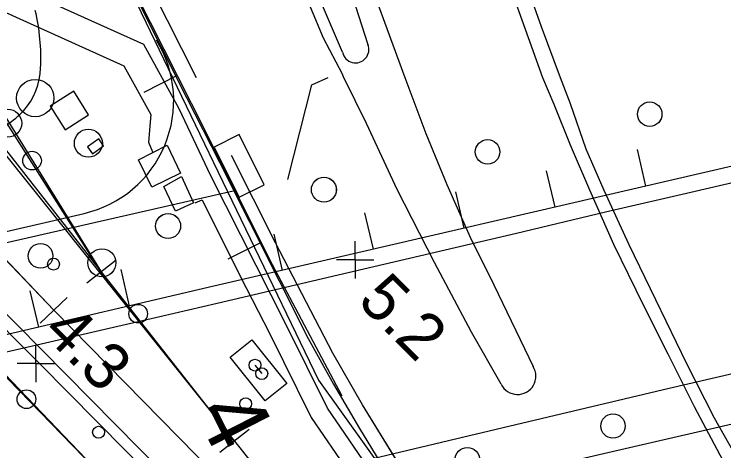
# Model space of a CAD drawing. Extents: x 1596643 to 1597288, y 13057194 to 13057957.
# Drawn here: x 1596926.19 to 1596964.23, y 13057439.15 to 13057462.53 of the extents above; entities that cross this region are included whole.
import ezdxf

# ---------------------------------------------------------------- set-up
doc = ezdxf.new("R2010")
doc.units = 0
for name, color, linetype in [('A Isolerskarv P', 7, 'Continuous'), ('A spårmitt L', 7, 'Continuous'), ('B kabelränna 400-500 mm NK L', 7, 'Continuous'), ('B kabelränna större än 500 mm NK L', 7, 'Continuous'), ('B växel linjevikt 0 L', 7, 'Continuous'), ('BAS bro ej def L', 7, 'Continuous'), ('BAS bro kantbalk ej def L', 7, 'Continuous'), ('BAS bropelare stöd ej def L', 7, 'Continuous'), ('BAS dagvatten brunn P', 7, 'Continuous'), ('BAS gång- cykelväg skymd L', 7, 'Continuous'), ('BAS jvg-bro kantbalk L', 7, 'Continuous'), ('BAS jvg-bro landfäste vinge L', 7, 'Continuous'), ('BAS Level 15', 7, 'Continuous'), ('BAS Level 16', 7, 'Continuous'), ('BAS Level 18', 7, 'Continuous'), ('BAS Level 29', 7, 'Continuous'), ('BAS Level 36', 7, 'Continuous'), ('BAS Level 37', 7, 'Continuous'), ('BAS markytetext T', 7, 'Continuous'), ('BAS stödmur fot L', 7, 'Continuous'), ('BAS stödmur krön L', 7, 'Continuous'), ('BAS vägbanekant L', 7, 'Continuous'), ('BAS vägbanekant skymd L', 7, 'Continuous'), ('C skåp kartsymbol P', 7, 'Continuous'), ('C skåp L', 7, 'Continuous'), ('C transformator L', 7, 'Continuous'), ('E ktlstolpe normal centrum P', 7, 'Continuous'), ('E sträva centrum P', 7, 'Continuous'), ('F signal fristående P', 7, 'Continuous')]:
    doc.layers.add(name, color=color, linetype=linetype)

msp = doc.modelspace()

# ---------------------------------------------------------------- linework, layer by layer
at = {"layer": 'A Isolerskarv P'}
for centre in [(1596925.84, 13057456.695), (1596925.84, 13057456.695), (1596930.886, 13057449.22), (1596930.886, 13057449.22)]:
    msp.add_circle(centre, 0.75, dxfattribs=at)
at = {"layer": 'A spårmitt L'}
for points in [[(1596861.603, 13057516.009), (1596866.442, 13057509.391), (1596878.849, 13057493.781), (1596895.097, 13057475.302), (1596900.34, 13057469.714), (1596931.231, 13057437.468), (1596933.8, 13057434.835)], [(1596887.988, 13057492.75), (1596889.66, 13057490.516), (1596900.094, 13057476.776), (1596906.53, 13057469.464), (1596928.328, 13057446.663), (1596936.899, 13057437.942), (1596957.336, 13057417.351), (1597001.928, 13057371.989), (1597034.879, 13057338.506), (1597063.764, 13057309.15)], [(1596906.028, 13057487.38), (1596921.777, 13057463.002), (1596931.207, 13057448.128)], [(1596907.066, 13057477.919), (1596920.191, 13057461.87), (1596938.351, 13057439.217), (1596949.208, 13057425.541)]]:
    msp.add_lwpolyline(points, dxfattribs=at)
at = {"layer": 'B kabelränna 400-500 mm NK L'}
msp.add_lwpolyline([(1596883.038, 13057480.441), (1596889.091, 13057474.53), (1596902.563, 13057461.987), (1596910.703, 13057454.289), (1596911.093, 13057454.69), (1596913.886, 13057457.525), (1596927.553, 13057443.815), (1596936.728, 13057434.552), (1596947.807, 13057423.165), (1596958.841, 13057412.087), (1596959.17, 13057412.506), (1596945.763, 13057426.086), (1596935.532, 13057436.607), (1596925.003, 13057447.233), (1596913.927, 13057458.386), (1596910.643, 13057455.068), (1596902.92, 13057462.372), (1596891.14, 13057473.364), (1596883.436, 13057480.826)], dxfattribs=at)
at = {"layer": 'B kabelränna större än 500 mm NK L'}
for points in [[(1596912.644, 13057489.282), (1596912.288, 13057489.11), (1596916.306, 13057480.961), (1596922.107, 13057468.716), (1596924.964, 13057462.97), (1596932.073, 13057459.771), (1596933.51, 13057457.153), (1596933.386, 13057455.673), (1596933.609, 13057455.161)], [(1596935.025, 13057457.474), (1596933.135, 13057460.919), (1596926.056, 13057464.105), (1596923.449, 13057469.348)], [(1596966.736, 13057411.707), (1596965.667, 13057412.984), (1596959.924, 13057419.384), (1596956.53, 13057423.046), (1596952.713, 13057427.821), (1596945.579, 13057437.659), (1596942.975, 13057441.442), (1596940.764, 13057445.894), (1596936.73, 13057453.881), (1596935.025, 13057457.474)], [(1596935.897, 13057452.432), (1596936.26, 13057452.588)], [(1596936.26, 13057452.588), (1596938.339, 13057448.441), (1596939.871, 13057445.444), (1596942.111, 13057440.933), (1596944.761, 13057437.083), (1596949.235, 13057430.863), (1596951.919, 13057427.212), (1596955.772, 13057422.393), (1596959.185, 13057418.71), (1596965.564, 13057411.602)]]:
    msp.add_lwpolyline(points, dxfattribs=at)
at = {"layer": 'B växel linjevikt 0 L'}
for p, q in [((1596930.874, 13057448.745), (1596921.659, 13057463.592)), ((1596930.874, 13057448.745), (1596921.659, 13057463.592)), ((1596930.874, 13057448.745), (1596920.075, 13057462.483)), ((1596930.874, 13057448.745), (1596920.075, 13057462.483)), ((1596928.31, 13057446.676), (1596915.42, 13057460.223)), ((1596928.31, 13057446.676), (1596915.42, 13057460.223)), ((1596930.874, 13057437.838), (1596918.078, 13057450.985)), ((1596930.874, 13057437.838), (1596918.078, 13057450.985)), ((1596931.661, 13057449.363), (1596930.088, 13057448.127)), ((1596931.661, 13057449.363), (1596930.088, 13057448.127)), ((1596938.006, 13057439.672), (1596930.874, 13057448.745)), ((1596938.006, 13057439.672), (1596930.874, 13057448.745)), ((1596929.034, 13057447.365), (1596927.586, 13057445.986)), ((1596929.034, 13057447.365), (1596927.586, 13057445.986)), ((1596938.792, 13057440.29), (1596937.22, 13057439.054)), ((1596938.792, 13057440.29), (1596937.22, 13057439.054))]:
    msp.add_line(p, q, dxfattribs=at)
at = {"layer": 'BAS bro ej def L'}
for points in [[(1596943.79, 13057460.493), (1596941.475, 13057465.89), (1596939.506, 13057470.621), (1596937.752, 13057475.401), (1596935.601, 13057481.7), (1596933.54, 13057487.886), (1596931.689, 13057493.846), (1596930.024, 13057499.204), (1596929.355, 13057502.374), (1596928.751, 13057505.014), (1596928.377, 13057506.696), (1596928.227, 13057507.736)], [(1596931.231, 13057501.323), (1596933.825, 13057493.971), (1596936.089, 13057487.752), (1596938.584, 13057480.625), (1596940.277, 13057475.775), (1596943.187, 13057467.026), (1596945.148, 13057460.913)]]:
    msp.add_lwpolyline(points, dxfattribs=at)
msp.add_arc((1596944.488, 13057460.641), 0.714, 191.9714, 22.3976, dxfattribs=at)
at = {"layer": 'BAS bro kantbalk ej def L'}
for p, q in [((1596930.096, 13057468.679), (1596935.426, 13057458.074)), ((1596935.426, 13057458.074), (1596937.194, 13057454.611))]:
    msp.add_line(p, q, dxfattribs=at)
at = {"layer": 'BAS bropelare stöd ej def L'}
for centre, radius in [((1596960.261, 13057457.18), 0.656), ((1596960.261, 13057457.18), 0.655), ((1596951.564, 13057455.161), 0.655), ((1596951.564, 13057455.161), 0.655), ((1596942.789, 13057453.136), 0.669), ((1596942.789, 13057453.136), 0.668), ((1596934.438, 13057451.188), 0.67), ((1596934.438, 13057451.189), 0.67), ((1596927.6, 13057449.592), 0.661), ((1596927.6, 13057449.592), 0.661), ((1596958.288, 13057440.48), 0.653), ((1596958.289, 13057440.48), 0.652), ((1596950.479, 13057438.666), 0.666), ((1596950.479, 13057438.666), 0.666)]:
    msp.add_circle(centre, radius, dxfattribs=at)
at = {"layer": 'BAS dagvatten brunn P'}
msp.add_line((1596938.247, 13057454.405), (1596938.247, 13057454.405), dxfattribs=at)
msp.add_line((1596938.247, 13057454.405), (1596938.247, 13057454.405), dxfattribs=at)
msp.add_lwpolyline([(1596936.902, 13057455.407), (1596938.252, 13057452.728), (1596939.592, 13057453.403), (1596938.242, 13057456.082)], close=True, dxfattribs=at)
msp.add_lwpolyline([(1596936.902, 13057455.407), (1596938.252, 13057452.728), (1596939.592, 13057453.403), (1596938.242, 13057456.082)], close=True, dxfattribs=at)
at = {"layer": 'BAS gång- cykelväg skymd L'}
msp.add_line((1596904.78, 13057446.035), (1596929.935, 13057451.867), dxfattribs=at)
for centre, radius, start, end in [((1596916.548, 13057460.18), 11.068, 357.2481, 13.3555), ((1596928.554, 13057457.895), 6.184, 282.9061, 31.6951), ((1596924.016, 13057459.756), 3.589, 318.4684, 358.2838), ((1596922.19, 13057461.743), 6.28, 294.2396, 315.9406)]:
    msp.add_arc(centre, radius, start, end, dxfattribs=at)
at = {"layer": 'BAS jvg-bro kantbalk L'}
for p, q in [((1596937.194, 13057454.611), (1596940.4, 13057448.249)), ((1596940.4, 13057448.249), (1596941.949, 13057445.162)), ((1596941.949, 13057445.162), (1596943.298, 13057442.722)), ((1596943.298, 13057442.722), (1596944.705, 13057440.352)), ((1596944.705, 13057440.352), (1596946.147, 13057437.981))]:
    msp.add_line(p, q, dxfattribs=at)
for centre, radius, start, end in [((1596754.249, 13057209.032), 283.999, 44.7736, 55.47706), ((1596747.882, 13057200.444), 290.055, 49.94104, 56.21521)]:
    msp.add_arc(centre, radius, start, end, dxfattribs=at)
at = {"layer": 'BAS jvg-bro landfäste vinge L'}
msp.add_lwpolyline([(1596908.173, 13057446.295), (1596908.918, 13057446.461), (1596937.924, 13057453.08)], dxfattribs=at)
at = {"layer": 'BAS Level 15'}
for centre in [(1596927.145, 13057454.69), (1596927.145, 13057454.69), (1596932.833, 13057446.493), (1596932.833, 13057446.493), (1596926.844, 13057441.914), (1596926.844, 13057441.914)]:
    msp.add_circle(centre, 0.5, dxfattribs=at)
at = {"layer": 'BAS Level 16'}
for p, q in [((1596944.473, 13057449.371), (1596944.473, 13057450.371)), ((1596944.473, 13057449.371), (1596944.473, 13057450.371)), ((1596944.473, 13057449.371), (1596943.473, 13057449.371)), ((1596944.473, 13057449.371), (1596943.473, 13057449.371)), ((1596944.473, 13057449.371), (1596945.473, 13057449.371)), ((1596944.473, 13057449.371), (1596944.473, 13057448.371)), ((1596944.473, 13057449.371), (1596945.473, 13057449.371)), ((1596944.473, 13057449.371), (1596944.473, 13057448.371)), ((1596927.344, 13057443.834), (1596927.344, 13057444.834)), ((1596927.344, 13057443.834), (1596927.344, 13057444.834)), ((1596927.344, 13057443.834), (1596926.344, 13057443.834)), ((1596927.344, 13057443.834), (1596926.344, 13057443.834)), ((1596927.344, 13057443.834), (1596928.344, 13057443.834)), ((1596927.344, 13057443.834), (1596927.344, 13057442.834)), ((1596927.344, 13057443.834), (1596928.344, 13057443.834)), ((1596927.344, 13057443.834), (1596927.344, 13057442.834))]:
    msp.add_line(p, q, dxfattribs=at)
at = {"layer": 'BAS Level 18'}
for p, q in [((1596934.926, 13057459.248), (1596933.141, 13057458.346)), ((1596934.926, 13057459.248), (1596933.141, 13057458.346)), ((1596960.056, 13057453.331), (1596959.604, 13057455.279)), ((1596960.056, 13057453.331), (1596959.604, 13057455.279)), ((1596955.185, 13057452.201), (1596954.733, 13057454.149)), ((1596955.185, 13057452.201), (1596954.733, 13057454.149)), ((1596950.314, 13057451.072), (1596949.862, 13057453.02)), ((1596950.314, 13057451.072), (1596949.862, 13057453.02)), ((1596945.443, 13057449.943), (1596944.991, 13057451.891)), ((1596945.443, 13057449.943), (1596944.991, 13057451.891)), ((1596940.573, 13057448.813), (1596940.121, 13057450.761)), ((1596940.573, 13057448.813), (1596940.121, 13057450.761)), ((1596939.421, 13057450.315), (1596937.634, 13057449.417)), ((1596939.421, 13057450.315), (1596937.634, 13057449.417)), ((1596932.371, 13057446.907), (1596931.917, 13057448.855)), ((1596932.371, 13057446.907), (1596931.917, 13057448.855)), ((1596927.501, 13057445.773), (1596927.047, 13057447.721)), ((1596927.501, 13057445.773), (1596927.047, 13057447.721))]:
    msp.add_line(p, q, dxfattribs=at)
at = {"layer": 'BAS Level 29'}
for centre in [(1596928.293, 13057449.149), (1596928.293, 13057449.149), (1596939.096, 13057443.739), (1596939.096, 13057443.739), (1596939.459, 13057443.286), (1596939.459, 13057443.286), (1596938.596, 13057441.672), (1596938.596, 13057441.672), (1596930.71, 13057440.147), (1596930.71, 13057440.147)]:
    msp.add_circle(centre, 0.318, dxfattribs=at)
at = {"layer": 'BAS Level 37'}
for points in [[(1596929.415, 13057470.053), (1596934.679, 13057459.15)], [(1596934.679, 13057459.15), (1596942.51, 13057442.931), (1596946.333, 13057437.601), (1596952.505, 13057428.568), (1596955.404, 13057424.94), (1596958.328, 13057421.412), (1596968.373, 13057410.821)]]:
    msp.add_lwpolyline(points, dxfattribs=at)
at = {"layer": 'BAS stödmur fot L'}
msp.add_lwpolyline([(1596940.857, 13057453.679), (1596942.144, 13057458.756), (1596943.017, 13057459.15)], dxfattribs=at)
at = {"layer": 'BAS stödmur krön L'}
for p, q in [((1596968.602, 13057455.312), (1596936.897, 13057447.961)), ((1596936.897, 13057447.961), (1596913.236, 13057442.45))]:
    msp.add_line(p, q, dxfattribs=at)
msp.add_lwpolyline([(1596910.214, 13057513.767), (1596911.127, 13057509.619), (1596913.141, 13057503.998), (1596916.093, 13057497.121), (1596921.06, 13057486.966), (1596925.519, 13057477.89), (1596930.551, 13057467.911), (1596935.677, 13057457.761), (1596940.017, 13057449.129), (1596943.748, 13057442.095)], dxfattribs=at)
at = {"layer": 'BAS vägbanekant L'}
for p, q in [((1596940.197, 13057450.291), (1596937.839, 13057454.961)), ((1596943.263, 13057444.387), (1596940.197, 13057450.291)), ((1596944.866, 13057441.615), (1596943.263, 13057444.387)), ((1596947.373, 13057437.534), (1596944.866, 13057441.615))]:
    msp.add_line(p, q, dxfattribs=at)
for points in [[(1596909.852, 13057526.126), (1596909.933, 13057524.265), (1596909.962, 13057521.856), (1596910.034, 13057520.017), (1596910.117, 13057518.411), (1596910.4, 13057516.123), (1596910.678, 13057514.709), (1596910.915, 13057513.499), (1596911.213, 13057512.126), (1596911.593, 13057510.742), (1596912.272, 13057508.493), (1596913.245, 13057505.826), (1596914.218, 13057503.383), (1596915.393, 13057500.633), (1596917.977, 13057495.093), (1596921.539, 13057487.973), (1596925.462, 13057480.018), (1596929.708, 13057471.482), (1596935.948, 13057459.15)], [(1596927.844, 13057508.45), (1596927.898, 13057507.778), (1596928.004, 13057506.639), (1596928.183, 13057505.683), (1596928.641, 13057503.862), (1596929.356, 13057500.566), (1596930.104, 13057497.788), (1596930.721, 13057495.174), (1596931.96, 13057491.022), (1596933.249, 13057486.525), (1596934.209, 13057483.411), (1596935.201, 13057480.632), (1596936.192, 13057477.68), (1596937.696, 13057473.73), (1596939.473, 13057469.291), (1596941.008, 13057465.453), (1596942.745, 13057461.268), (1596943.762, 13057459.333), (1596943.84, 13057459.15)], [(1596938.443, 13057507.097), (1596939.799, 13057503.927), (1596940.93, 13057500.659), (1596942.141, 13057497.148), (1596944.544, 13057490.297), (1596946.684, 13057483.854), (1596949.527, 13057475.711), (1596952.17, 13057468.27), (1596954.433, 13057461.878), (1596955.457, 13057459.15)], [(1596938.502, 13057504.668), (1596939.595, 13057501.774), (1596940.997, 13057497.956), (1596943.059, 13057491.941), (1596945.29, 13057485.345), (1596947.892, 13057477.884), (1596950.765, 13057469.629), (1596954.512, 13057459.15)], [(1596931.373, 13057503.574), (1596932.345, 13057501.048), (1596934.657, 13057494.452), (1596936.87, 13057488.223), (1596939.531, 13057480.396), (1596942.084, 13057473.057), (1596943.906, 13057467.916), (1596947.131, 13057459.15)], [(1596952.295, 13057442.72), (1596950.699, 13057445.509), (1596948.729, 13057449.234), (1596946.719, 13057453.153), (1596945.074, 13057456.674), (1596943.852, 13057459.15)], [(1596947.131, 13057459.15), (1596948.263, 13057456.146), (1596949.382, 13057453.419), (1596950.634, 13057450.59), (1596951.896, 13057448.046), (1596954.006, 13057443.67)], [(1596954.512, 13057459.15), (1596955.118, 13057457.72), (1596955.995, 13057455.532), (1596957.034, 13057453.131), (1596958.315, 13057450.221), (1596959.9, 13057446.974), (1596961.223, 13057444.348), (1596962.637, 13057441.519), (1596964.021, 13057438.944), (1596965.364, 13057436.562), (1596966.8, 13057434.271), (1596968.373, 13057431.554)], [(1596955.457, 13057459.15), (1596956.002, 13057457.758), (1596956.837, 13057455.316), (1596957.796, 13057453.108), (1596959.138, 13057450.198), (1596960.562, 13057447.257), (1596962.227, 13057443.827), (1596963.712, 13057440.926), (1596965.086, 13057438.494), (1596966.41, 13057436.223), (1596967.803, 13057433.92)], [(1596940.197, 13057450.291), (1596937.839, 13057454.961)], [(1596943.263, 13057444.387), (1596940.197, 13057450.291)], [(1596944.866, 13057441.615), (1596943.263, 13057444.387)], [(1596947.373, 13057437.534), (1596944.866, 13057441.615)]]:
    msp.add_lwpolyline(points, dxfattribs=at)
msp.add_arc((1596953.176, 13057443.149), 0.98, 205.9636, 32.1169, dxfattribs=at)
at = {"layer": 'BAS vägbanekant skymd L'}
for points in [[(1596975.549, 13057456.294), (1596969.153, 13057454.536), (1596962.688, 13057453.046), (1596957.894, 13057451.93), (1596953.113, 13057450.794), (1596943.549, 13057448.559), (1596937.074, 13057447.044), (1596934.001, 13057446.332), (1596924.437, 13057444.133), (1596915.451, 13057442.034), (1596910.392, 13057440.886), (1596910.146, 13057440.853), (1596910.392, 13057440.886)], [(1596979.346, 13057446.739), (1596968.227, 13057444.103), (1596961.305, 13057442.487), (1596952.401, 13057440.381), (1596943.603, 13057438.303), (1596934.215, 13057436.081), (1596926.33, 13057434.208), (1596921.412, 13057433.046), (1596921.21, 13057432.997), (1596921.412, 13057433.046)], [(1596980.34, 13057444.249), (1596976.126, 13057443.26), (1596966.766, 13057441.06), (1596957.541, 13057438.93), (1596947.883, 13057436.681), (1596938.321, 13057434.458), (1596928.922, 13057432.26), (1596924.04, 13057431.112), (1596923.794, 13057431.055), (1596924.04, 13057431.112)]]:
    msp.add_lwpolyline(points, dxfattribs=at)
at = {"layer": 'C skåp kartsymbol P'}
for p, q in [((1596937.763, 13057444.166), (1596938.933, 13057445.104)), ((1596937.763, 13057444.166), (1596938.933, 13057445.104)), ((1596938.933, 13057445.104), (1596940.809, 13057442.764)), ((1596938.933, 13057445.104), (1596940.809, 13057442.764)), ((1596939.639, 13057441.826), (1596937.763, 13057444.166)), ((1596939.639, 13057441.826), (1596937.763, 13057444.166)), ((1596939.286, 13057443.465), (1596939.286, 13057443.465)), ((1596939.286, 13057443.465), (1596939.286, 13057443.465)), ((1596940.809, 13057442.764), (1596939.639, 13057441.826)), ((1596940.809, 13057442.764), (1596939.639, 13057441.826))]:
    msp.add_line(p, q, dxfattribs=at)
at = {"layer": 'C skåp L'}
msp.add_line((1596939.096, 13057443.739), (1596939.459, 13057443.286), dxfattribs=at)
msp.add_lwpolyline([(1596930.717, 13057455.864), (1596930.114, 13057455.428), (1596930.38, 13057455.051), (1596930.983, 13057455.486), (1596930.717, 13057455.864)], dxfattribs=at)
at = {"layer": 'C transformator L'}
for points in [[(1596932.851, 13057454.737), (1596934.396, 13057455.518), (1596935.095, 13057454.024), (1596933.569, 13057453.27), (1596932.851, 13057454.737)], [(1596934.838, 13057451.977), (1596934.203, 13057453.31), (1596935.158, 13057453.834), (1596935.805, 13057452.439), (1596934.838, 13057451.977)]]:
    msp.add_lwpolyline(points, dxfattribs=at)
at = {"layer": 'E ktlstolpe normal centrum P'}
msp.add_circle((1596930.163, 13057455.623), 0.75, dxfattribs=at)
msp.add_circle((1596930.163, 13057455.623), 0.75, dxfattribs=at)
at = {"layer": 'E sträva centrum P'}
for p, q in [((1596929.376, 13057458.415), (1596928.109, 13057457.612)), ((1596929.376, 13057458.415), (1596928.109, 13057457.612)), ((1596930.179, 13057457.148), (1596929.376, 13057458.415)), ((1596930.179, 13057457.148), (1596929.376, 13057458.415)), ((1596928.109, 13057457.612), (1596928.912, 13057456.345)), ((1596928.109, 13057457.612), (1596928.912, 13057456.345)), ((1596928.912, 13057456.345), (1596930.179, 13057457.148)), ((1596928.912, 13057456.345), (1596930.179, 13057457.148)), ((1596929.144, 13057457.38), (1596929.144, 13057457.38)), ((1596929.144, 13057457.38), (1596929.144, 13057457.38))]:
    msp.add_line(p, q, dxfattribs=at)
at = {"layer": 'F signal fristående P'}
msp.add_circle((1596927.313, 13057458.043), 1, dxfattribs=at)
msp.add_circle((1596927.313, 13057458.043), 1, dxfattribs=at)

# ---------------------------------------------------------------- texts
at = {"layer": 'BAS Level 36'}
msp.add_text('4', height=3.5, rotation=296.9611, dxfattribs=at).set_placement((1596935.851, 13057441.199))
at = {"layer": 'BAS markytetext T'}
for s, p in [('5.2', (1596944.525, 13057447.108)), ('4.3', (1596927.628, 13057445.455))]:
    msp.add_text(s, height=2.5, rotation=315, dxfattribs=at).set_placement(p)

doc.saveas('drawing.dxf')
